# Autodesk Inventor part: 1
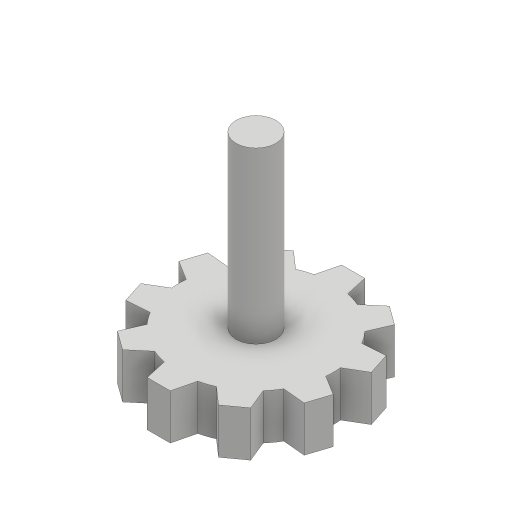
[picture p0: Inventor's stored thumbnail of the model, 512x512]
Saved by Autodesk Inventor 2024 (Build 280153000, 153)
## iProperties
Created: 2017-05
Part Number: 1
Material: Generic
Document SubType Name: Modeling
Designer: CADCIM 00
Density: 1 g/cm^3
Appearance: Default
Author: CADCIM 00
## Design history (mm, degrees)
sketch "Sketch1"
  geometry: L1 (-3.765, 16.614)-(-2.561, 21.495); L2 (-2.561, 21.495)-(2.518, 21.495); L3 (2.518, 21.495)-(3.613, 16.648); L4 (-12.811, 11.228)-(-14.706, 15.884); L5 (-14.706, 15.884)-(-10.598, 18.87); L6 (-10.598, 18.87)-(-6.862, 15.592); L7 (-16.964, 1.554)-(-21.234, 4.206); L8 (-21.234, 4.206)-(-19.665, 9.037); L9 (-19.665, 9.037)-(-14.716, 8.581); L10 (-14.637, -8.714)-(-19.651, -9.078); L11 (-19.651, -9.078)-(-21.221, -4.248); L12 (-21.221, -4.248)-(-16.949, -1.708); L13 (-6.72, -15.654)-(-10.562, -18.895); L14 (-10.562, -18.895)-(-14.671, -15.91); L15 (-14.671, -15.91)-(-12.708, -11.344); L16 (3.765, -16.614)-(2.561, -21.495); L17 (2.561, -21.495)-(-2.518, -21.495); L18 (-2.518, -21.495)-(-3.613, -16.648); L19 (12.811, -11.228)-(14.706, -15.884); L20 (14.706, -15.884)-(10.598, -18.87); L21 (10.598, -18.87)-(6.862, -15.592); L22 (16.964, -1.554)-(21.234, -4.206); L23 (21.234, -4.206)-(19.665, -9.037); L24 (19.665, -9.037)-(14.716, -8.581); L25 (14.637, 8.714)-(19.651, 9.078); L26 (19.651, 9.078)-(21.221, 4.248); L27 (21.221, 4.248)-(16.949, 1.708); L28 (6.72, 15.654)-(10.562, 18.895); L29 (10.562, 18.895)-(14.671, 15.91); L30 (14.671, 15.91)-(12.708, 11.344); A1 r 17.035 centre (0, 0) between (-3.765, 16.614) and (-6.862, 15.592); A2 r 17.035 centre (0, 0) between (-12.811, 11.228) and (-14.716, 8.581); A3 r 17.035 centre (0, 0) between (-16.964, 1.554) and (-16.949, -1.708); A4 r 17.035 centre (0, 0) between (-14.637, -8.714) and (-12.708, -11.344); A5 r 17.035 centre (0, 0) between (-6.72, -15.654) and (-3.613, -16.648); A6 r 17.035 centre (0, 0) between (3.765, -16.614) and (6.862, -15.592); A7 r 17.035 centre (0, 0) between (12.811, -11.228) and (14.716, -8.581); A8 r 17.035 centre (0, 0) between (16.964, -1.554) and (16.949, 1.708); A9 r 17.035 centre (0, 0) between (14.637, 8.714) and (12.708, 11.344); A10 r 17.035 centre (0, 0) between (6.72, 15.654) and (3.613, 16.648); 1 further point
  constraints: 60 end point, 20 point on circle, 10 centre point, 1 coincident, 1 horizontal, 71 other
  dimensions: "d2" = 360 deg dimension on A1.centre L1.start (derived)
extrude "Extrusion1" new body sketch "Sketch1" distance "d4" = 10; taper "d5" = 0 deg
sketch "Sketch2"
  geometry: C1 r 4.406 at (0, 0); 1 further point
  constraints: 1 centre point, 1 coincident
extrude "Extrusion2" join sketch "Sketch2" distance "d6" = 37.5; taper "d7" = 0 deg
body "Solid1"
